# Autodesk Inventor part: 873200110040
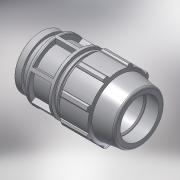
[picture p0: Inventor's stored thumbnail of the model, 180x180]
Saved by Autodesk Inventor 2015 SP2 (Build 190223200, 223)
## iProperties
Created: 2017-02
Part Number: 873200110040
Material: PVC-Piping
Description: PLASSON SHOULDERED ADAPTOR 110-4"
Document SubType Name: Modeling
Designer: KIM
Mass: 92.6774 g
Surface Area: 199.44 cm^2
Volume: 66.1981 cm^3
Density: 1.4 g/cm^3
Appearance: Smooth - White
Author: KIM
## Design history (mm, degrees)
derived "87320.ipt"
feature "Solid1::87320.ipt"
tag "TaggingFeature1"
body "Solid1"
other parameters: "d4" = 36.71429, "d5" = 51.4, "d7" = 181, "d8" = 135.75, "d9" = 36.71429, "d11" = 9.17857, "d12" = 144.8, "d13" = 120 deg, "d15" = 8 deg, "d16" = 162.9, "d18" = 5, "d19" = 35 deg, "d20" = 17.5 deg, "d21" = 168.33, "d23" = 0, "d25" = 360 deg, "d27" = 3.62, "d34" = 9.05, "d36" = 0, "d42" = 77.1, "d43" = 5.43, "d46" = 3, "d49" = 215, "d51" = 257, "d53" = 2, "d55" = 360 deg, "d57" = 123, "d59" = 51.4, "d61" = 110.7, "d62" = 16, "d64" = 6.68571, "d66" = 154.755, "d67" = 6.68571, "d70" = 86.1, "d71" = 73.8, "d73" = 6.15, "d74" = 16, "E_" = 181, "H_" = 257, "l_" = 215, "L_" = 16, "B_" = 123, "d63" = 26.74286, "d72" = 18.45
